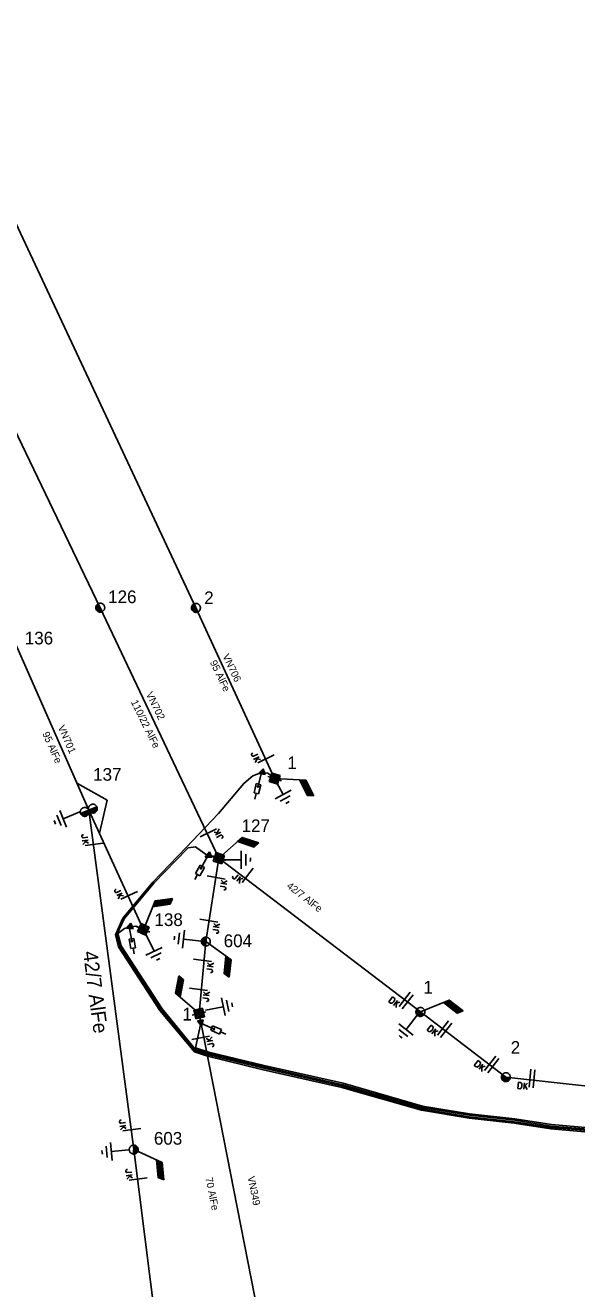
# Model space of a CAD drawing. Extents: x -536397 to -535454, y -1201642 to -1200953.
# Drawn here: x -536253.8 to -536177.8, y -1201334.5 to -1201160.3 of the extents above; entities that cross this region are included whole.
import ezdxf

# ---------------------------------------------------------------- set-up
doc = ezdxf.new("R2010")
doc.units = 0
for name, color, linetype in [('DOPLŇ_POPISY', 7, 'Continuous'), ('ELE_EON', 7, 'Continuous'), ('ELE_EON_POPIS', 7, 'Continuous'), ('Implicitní', 7, 'Continuous'), ('KN_HRAN_PODZEM', 7, 'Continuous'), ('KN_HRAN_POHYBLIVÁ', 7, 'Continuous'), ('KN_HRAN_STÁTNÍ', 7, 'Continuous'), ('KONEC_VEDENÍ', 7, 'Continuous'), ('PB_NN', 7, 'Continuous'), ('PLG_EXPORT_GPE', 7, 'Continuous'), ('PODZEM_NN_POPIS', 7, 'Continuous'), ('PROJEKT', 7, 'Continuous'), ('RÁMEČEK', 7, 'Continuous'), ('SDEL_EON', 7, 'Continuous'), ('SDEL_EON_POPIS', 7, 'Continuous'), ('SR', 7, 'Continuous'), ('TECH_OCHR_PÁSMO_HRAN', 7, 'Continuous')]:
    doc.layers.add(name, color=color, linetype=linetype)

# ---------------------------------------------------------------- blocks, each defined once
blk = doc.blocks.new('VN850')
at = {"layer": 'RÁMEČEK'}
for points in [[(-0.56, 1.43), (-0.56, -1.07)], [(-0.01, 1.43), (-0.01, -1.07)], [(-2.09, -0.54), (-1.78, -0.54)], [(-2.09, -1.41), (-2.09, -0.54)], [(-1.78, -1.41), (-2.09, -1.41)], [(-1.78, -0.54), (-1.66, -0.6)], [(-1.67, -1.35), (-1.78, -1.41)], [(-1.59, -1.2), (-1.67, -1.35)], [(-1.66, -0.6), (-1.59, -0.75)], [(-1.59, -0.75), (-1.55, -0.96)], [(-1.55, -0.96), (-1.59, -1.2)], [(-1.26, -0.54), (-1.26, -1.41)], [(-0.85, -0.54), (-1.26, -1.09)], [(-1.13, -0.92), (-0.77, -1.41)]]:
    blk.add_lwpolyline(points, dxfattribs=at)
blk = doc.blocks.new('VN840')
at = {"layer": 'RÁMEČEK'}
for points in [[(-0.01, 1.41), (-0.01, -1.09)], [(-1.51, -1.24), (-1.51, -1.15)], [(-1.48, -1.35), (-1.51, -1.24)], [(-1.33, -1.42), (-1.48, -1.35)], [(-1.27, -1.42), (-1.33, -1.42)], [(-1.13, -1.35), (-1.27, -1.42)], [(-1.09, -1.24), (-1.13, -1.35)], [(-1.09, -0.59), (-1.09, -1.24)], [(-0.68, -0.59), (-0.68, -1.42)], [(-0.68, -1.11), (-0.27, -0.59)], [(-0.54, -0.94), (-0.2, -1.42)]]:
    blk.add_lwpolyline(points, dxfattribs=at)
blk = doc.blocks.new('VN860')
at = {"layer": 'RÁMEČEK'}
for points in [[(-3.74, 0), (0.01, 2.82)], [(0.01, 2.82), (3.76, 0)]]:
    blk.add_lwpolyline(points, dxfattribs=at)
blk = doc.blocks.new('VN890')
at = {"layer": 'SDEL_EON_POPIS'}
for points in [[(-0.41, 0.41), (0.41, 0)], [(-0.41, -0.41), (-0.41, 0.41)], [(0.41, 0), (-0.41, -0.41)], [(-0.34, 0.31), (0.27, 0), (-0.34, -0.3), (-0.34, 0.31)], [(-0.26, 0.2), (0.1, 0), (-0.26, -0.18), (-0.26, 0.2)], [(-0.19, 0.09), (-0.04, 0), (-0.19, -0.08), (-0.19, 0.09)], [(-0.16, -0.01), (-0.16, 0.03), (-0.13, 0.01), (-0.16, -0.01)]]:
    blk.add_lwpolyline(points, dxfattribs=at)
blk = doc.blocks.new('VN820')
at = {"layer": 'DOPLŇ_POPISY'}
for points in [[(0, 0), (0, -2.1)], [(-0.32, -1.63), (0.34, -1.63)], [(-0.32, -2.95), (-0.32, -1.63)], [(0.34, -1.63), (0.34, -2.95)], [(0.34, -2.95), (-0.32, -2.95)], [(0, -2.1), (-0.12, -1.86)], [(0, -2.1), (0.12, -1.86)], [(0, -2.95), (0, -3.75)]]:
    blk.add_lwpolyline(points, dxfattribs=at)
blk = doc.blocks.new('VN810')
at = {"layer": 'PLG_EXPORT_GPE'}
for points in [[(0, -1.25), (0, -3.75)], [(1.25, -3.75), (-1.25, -3.75)], [(0.77, -4.37), (-0.8, -4.37)], [(0, -5), (-0.25, -5)], [(0.27, -5), (0, -5)]]:
    blk.add_lwpolyline(points, dxfattribs=at)
blk = doc.blocks.new('VN001')
at = {"layer": 'Implicitní'}
for p, q in [((2.02, 3.53), (4.43, 3.53)), ((2.05, 3.58), (4.46, 3.58)), ((2.07, 3.63), (4.49, 3.63)), ((2.1, 3.68), (4.52, 3.68)), ((2.13, 3.73), (2.54, 3.73)), ((1.73, 3.03), (4.14, 3.03)), ((1.76, 3.08), (4.17, 3.08)), ((1.79, 3.13), (4.2, 3.13)), ((1.82, 3.18), (4.23, 3.18)), ((1.85, 3.23), (4.26, 3.23)), ((1.87, 3.28), (4.29, 3.28)), ((1.9, 3.33), (4.32, 3.33)), ((1.93, 3.38), (4.35, 3.38)), ((1.96, 3.43), (4.37, 3.43)), ((1.99, 3.48), (4.4, 3.48))]:
    blk.add_line(p, q, dxfattribs=at)
blk.add_lwpolyline([(2.13, 3.73), (0, 0)], dxfattribs=at)
blk.add_lwpolyline([(4.55, 3.73), (2.13, 3.73), (1.7, 2.98), (4.12, 2.99)], close=True, dxfattribs=at)
blk = doc.blocks.new('VN440')
at = {"layer": 'ELE_EON_POPIS'}
for points in [[(1.22, 0), (1.21, 0.13), (1.19, 0.25), (1.16, 0.38), (1.11, 0.5), (1.05, 0.61), (0.98, 0.72), (0.9, 0.82), (0.81, 0.91), (0.71, 0.99), (0.6, 1.06), (0.49, 1.12), (0.37, 1.16), (0.25, 1.2), (0.12, 1.22), (-0.01, 1.22), (-0.14, 1.22), (-0.26, 1.2), (-0.39, 1.16), (-0.51, 1.12), (-0.62, 1.06), (-0.73, 0.99), (-0.83, 0.91), (-0.92, 0.82), (-1, 0.72), (-1.07, 0.61), (-1.13, 0.5), (-1.18, 0.38), (-1.21, 0.25), (-1.23, 0.13), (-1.24, 0), (-1.23, -0.13), (-1.21, -0.26), (-1.18, -0.38), (-1.13, -0.5), (-1.07, -0.62), (-1, -0.73), (-0.92, -0.83), (-0.83, -0.92), (-0.73, -1), (-0.62, -1.07), (-0.51, -1.13), (-0.39, -1.17), (-0.26, -1.2), (-0.14, -1.23), (-0.01, -1.23), (0.12, -1.23), (0.25, -1.2), (0.37, -1.17), (0.49, -1.13), (0.6, -1.07), (0.71, -1), (0.81, -0.92), (0.9, -0.83), (0.98, -0.73), (1.05, -0.62), (1.11, -0.5), (1.16, -0.38), (1.19, -0.26), (1.21, -0.13), (1.22, 0)], [(-1.24, 0), (1.22, 0)], [(-1.18, -0.34), (1.1, -0.34)], [(-1.01, -0.63), (0.97, -0.63)], [(-0.74, -0.92), (0.68, -0.92)]]:
    blk.add_lwpolyline(points, dxfattribs=at)
blk = doc.blocks.new('VN470')
at = {"layer": 'ELE_EON_POPIS'}
for points in [[(-1.23, 1.22), (1.23, 1.22)], [(-1.23, -1.23), (-1.23, 1.22)], [(-0.92, 0.9), (0.92, 0.9)], [(-0.92, -0.95), (-0.92, 0.9)], [(-0.61, 0.61), (0.61, 0.61)], [(-0.61, -0.62), (-0.61, 0.61)], [(-0.31, -0.27), (-0.31, 0.34)], [(-0.31, 0.34), (0.31, 0.34)], [(0, 1.22), (0, 1.97)], [(0.31, 0.34), (0.31, -0.27)], [(0.61, 0.61), (0.61, -0.62)], [(0.92, 0.9), (0.92, -0.95)], [(1.23, 1.22), (1.23, -1.23)], [(1.23, -1.23), (-1.23, -1.23)], [(0.92, -0.95), (-0.92, -0.95)], [(0.61, -0.62), (-0.61, -0.62)], [(0.31, -0.27), (-0.31, -0.27)], [(0, -1.23), (0, -1.98)]]:
    blk.add_lwpolyline(points, dxfattribs=at)
blk = doc.blocks.new('VN450')
at = {"layer": 'ELE_EON_POPIS'}
for points in [[(0, 0), (-0.01, 0.13), (-0.03, 0.25), (-0.06, 0.38), (-0.11, 0.5), (-0.16, 0.61), (-0.23, 0.72), (-0.31, 0.82), (-0.4, 0.91), (-0.5, 0.99), (-0.61, 1.06), (-0.72, 1.11), (-0.84, 1.16), (-0.97, 1.19), (-1.09, 1.21), (-1.22, 1.22), (-1.35, 1.21), (-1.47, 1.19), (-1.59, 1.16), (-1.71, 1.11), (-1.83, 1.06), (-1.93, 0.99), (-2.03, 0.91), (-2.12, 0.82), (-2.2, 0.72), (-2.27, 0.61), (-2.33, 0.5), (-2.38, 0.38), (-2.41, 0.25), (-2.43, 0.13), (-2.44, 0), (-2.43, -0.13), (-2.41, -0.25), (-2.38, -0.38), (-2.33, -0.5), (-2.27, -0.61), (-2.2, -0.72), (-2.12, -0.82), (-2.03, -0.91), (-1.93, -0.99), (-1.83, -1.06), (-1.71, -1.11), (-1.59, -1.16), (-1.47, -1.19), (-1.35, -1.21), (-1.22, -1.22), (-1.09, -1.21), (-0.97, -1.19), (-0.84, -1.16), (-0.72, -1.11), (-0.61, -1.06), (-0.5, -0.99), (-0.4, -0.91), (-0.31, -0.82), (-0.23, -0.72), (-0.16, -0.61), (-0.11, -0.5), (-0.06, -0.38), (-0.03, -0.25), (-0.01, -0.13), (0, 0)], [(-2.44, 0), (2.44, 0)], [(2.44, 0), (2.43, 0.13), (2.41, 0.25), (2.38, 0.38), (2.33, 0.5), (2.27, 0.61), (2.2, 0.72), (2.12, 0.82), (2.03, 0.91), (1.94, 0.99), (1.83, 1.06), (1.71, 1.11), (1.6, 1.16), (1.47, 1.19), (1.35, 1.21), (1.22, 1.22), (1.09, 1.21), (0.97, 1.19), (0.84, 1.16), (0.72, 1.11), (0.61, 1.06), (0.5, 0.99), (0.4, 0.91), (0.31, 0.82), (0.23, 0.72), (0.16, 0.61), (0.11, 0.5), (0.06, 0.38), (0.03, 0.25), (0.01, 0.13), (0, 0), (0.01, -0.13), (0.03, -0.25), (0.06, -0.38), (0.11, -0.5), (0.16, -0.61), (0.23, -0.72), (0.31, -0.82), (0.4, -0.91), (0.5, -0.99), (0.61, -1.06), (0.72, -1.11), (0.84, -1.16), (0.97, -1.19), (1.09, -1.21), (1.22, -1.22), (1.35, -1.21), (1.47, -1.19), (1.6, -1.16), (1.71, -1.11), (1.83, -1.06), (1.94, -0.99), (2.03, -0.91), (2.12, -0.82), (2.2, -0.72), (2.27, -0.61), (2.33, -0.5), (2.38, -0.38), (2.41, -0.25), (2.43, -0.13), (2.44, 0)], [(-2.4, -0.31), (-0.04, -0.31)], [(-2.26, -0.61), (-0.17, -0.61)], [(-2.01, -0.92), (-0.42, -0.92)], [(0.04, -0.31), (2.4, -0.31)], [(0.17, -0.61), (2.27, -0.61)], [(0.42, -0.92), (2.02, -0.92)]]:
    blk.add_lwpolyline(points, dxfattribs=at)

msp = doc.modelspace()

# ---------------------------------------------------------------- linework, layer by layer
at = {"layer": 'ELE_EON'}
for points in [[(-536219.44, -1201264.18), (-536230.28, -1201240.65), (-536267.93, -1201160.31)], [(-536279.58, -1201165.38), (-536243.47, -1201240.62), (-536227.12, -1201275.16)], [(-536289.66, -1201170.08), (-536254.73, -1201246.52), (-536245.05, -1201268.55)], [(-536245.05, -1201268.55), (-536237.69, -1201284.62)], [(-536229.86, -1201296.57), (-536218.36, -1201355.13), (-536212.54, -1201404.88), (-536207.27, -1201451.49)]]:
    msp.add_lwpolyline(points, dxfattribs=at)
at = {"layer": 'PODZEM_NN_POPIS'}
for points in [[(-536245.05, -1201268.55), (-536238.86, -1201315.34)], [(-536227.12, -1201275.16), (-536228.92, -1201286.65)], [(-536228.92, -1201286.65), (-536229.86, -1201296.57)], [(-536238.86, -1201315.34), (-536232.78, -1201363.5), (-536227.13, -1201407.48), (-536207.27, -1201451.49)]]:
    msp.add_lwpolyline(points, dxfattribs=at)
at = {"layer": 'PROJEKT'}
for points in [[(-536174.08, -1201313.11), (-536181.38, -1201312.49), (-536186.41, -1201311.69), (-536192.65, -1201311.01), (-536199.22, -1201309.92), (-536210.16, -1201306.78), (-536221.01, -1201304.32), (-536228.67, -1201302.47), (-536230.49, -1201301.88), (-536235.26, -1201296.17), (-536240.98, -1201287.39), (-536241.39, -1201285.72), (-536240.35, -1201283.41), (-536236.24, -1201278.45), (-536231.61, -1201273.69), (-536227.17, -1201268.98), (-536223.69, -1201264.85), (-536222.46, -1201263.79), (-536221.26, -1201263.36), (-536220.36, -1201263.43), (-536219.44, -1201264.18)], [(-536174.06, -1201312.91), (-536181.35, -1201312.29), (-536186.38, -1201311.49), (-536192.62, -1201310.81), (-536199.17, -1201309.73), (-536210.1, -1201306.59), (-536220.96, -1201304.13), (-536228.62, -1201302.28), (-536230.43, -1201301.69), (-536235.1, -1201296.05), (-536240.79, -1201287.31), (-536241.2, -1201285.67), (-536240.17, -1201283.51), (-536236.1, -1201278.59), (-536231.47, -1201273.83), (-536231.37, -1201273.73), (-536230.35, -1201273.57), (-536228.63, -1201274.83), (-536227.12, -1201275.16)], [(-536174.04, -1201312.71), (-536181.33, -1201312.09), (-536186.36, -1201311.29), (-536192.6, -1201310.61), (-536199.13, -1201309.53), (-536210.06, -1201306.39), (-536220.92, -1201303.93), (-536228.56, -1201302.08), (-536230.37, -1201301.5), (-536234.94, -1201295.93), (-536240.6, -1201287.23), (-536241.03, -1201285.53), (-536240.15, -1201284.85), (-536239.48, -1201284.67), (-536238.55, -1201284.55), (-536237.53, -1201285.03)], [(-536174.02, -1201312.51), (-536181.3, -1201311.89), (-536186.33, -1201311.09), (-536192.57, -1201310.41), (-536199.08, -1201309.34), (-536210.01, -1201306.2), (-536220.87, -1201303.74), (-536228.51, -1201301.89), (-536230.34, -1201301.29), (-536229.6, -1201297.92), (-536229.77, -1201296.93)]]:
    msp.add_lwpolyline(points, dxfattribs=at)
at = {"layer": 'SDEL_EON_POPIS'}
for points in [[(-536227.12, -1201275.16), (-536199.36, -1201296.36)], [(-536199.36, -1201296.36), (-536187.58, -1201305.35), (-536149.67, -1201309.55)]]:
    msp.add_lwpolyline(points, dxfattribs=at)

# ---------------------------------------------------------------- block references
at = {"layer": 'DOPLŇ_POPISY'}
for name, p, xscale, yscale, rotation in [('VN440', (-536243.47, -1201240.62), 0.5, 0.49999999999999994, -64.4647500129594), ('VN440', (-536230.28, -1201240.65), 0.5, 0.5, -64.87521117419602), ('VN470', (-536219.44, -1201264.18), 0.4999999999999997, 0.49999999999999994, -107.11528296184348), ('VN450', (-536245.05, -1201268.55), 0.49999999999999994, 0.5000000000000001, 22.397824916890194), ('VN470', (-536227.12, -1201275.16), 0.5, 0.5, 71.20198082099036), ('VN470', (-536237.53, -1201284.96), 0.5000000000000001, 0.5000000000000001, -114.08686544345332), ('VN440', (-536228.92, -1201286.66), 0.5000000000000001, 0.5, -96.35033613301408), ('VN470', (-536229.86, -1201296.57), 0.4999999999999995, 0.4999999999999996, -76.94533903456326), ('VN440', (-536199.35, -1201296.36), 0.49999999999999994, 0.5000000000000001, -37.8457360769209), ('VN440', (-536187.57, -1201305.35), 0.5, 0.5, -37.83150002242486), ('VN440', (-536238.86, -1201315.33), 0.5, 0.5000000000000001, 86.69934168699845)]:
    msp.add_blockref(name, p, dxfattribs=dict(at, xscale=xscale, yscale=yscale, rotation=rotation))
at = {"layer": 'KN_HRAN_PODZEM'}
for p, rotation in [((-536221.26, -1201263.36), -160.28570550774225), ((-536228.63, -1201274.83), -154.34267780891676), ((-536239.48, -1201284.67), -158.4331499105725), ((-536229.61, -1201297.92), -78.9704277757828)]:
    msp.add_blockref('VN890', p, dxfattribs=dict(at, rotation=rotation))
at = {"layer": 'KN_HRAN_POHYBLIVÁ'}
for name, p, rotation in [('VN840', (-536220.76, -1201261.54), -64.61845551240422), ('VN860', (-536245.11, -1201268.29), -66.11288332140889), ('VN840', (-536244.45, -1201273.27), -82.48772505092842), ('VN840', (-536228.44, -1201271.57), 116.1480499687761), ('VN840', (-536223.24, -1201277.64), -37.84615556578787), ('VN840', (-536239.63, -1201280.35), -65.56397498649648), ('VN840', (-536227.33, -1201277.84), 80.1997222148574), ('VN840', (-536228.36, -1201283.8), 80.1997222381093), ('VN840', (-536229.22, -1201289.26), 82.13469442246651), ('VN840', (-536229.77, -1201293.24), 82.13469442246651), ('VN850', (-536201.2, -1201295.11), -37.84615554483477), ('VN850', (-536195.91, -1201299.05), -37.83080836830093), ('VN840', (-536229.49, -1201299.89), 101.4130471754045), ('VN850', (-536189.41, -1201303.92), -37.83080836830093), ('VN850', (-536183.71, -1201305.74), -6.180297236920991), ('VN840', (-536239.26, -1201312.62), -82.48772501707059), ('VN840', (-536238.39, -1201319.44), -82.79501113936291)]:
    msp.add_blockref(name, p, dxfattribs=dict(at, rotation=rotation))
at = {"layer": 'KN_HRAN_STÁTNÍ'}
for p, rotation in [((-536221.26, -1201263.36), -13.990508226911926), ((-536228.63, -1201274.83), -28.8901470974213), ((-536239.48, -1201284.67), 10.619655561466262), ((-536229.61, -1201297.92), 66.19975004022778)]:
    msp.add_blockref('VN820', p, dxfattribs=dict(at, rotation=rotation))
at = {"layer": 'RÁMEČEK'}
for p, rotation in [((-536220.03, -1201263.08), 28.219202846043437), ((-536245.11, -1201268.29), -67.60749723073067), ((-536227.79, -1201275.36), 89.79945003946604), ((-536237.69, -1201284.62), 25.76595266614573), ((-536228.29, -1201286.72), -96.34631667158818), ((-536230.2, -1201296.37), 101.36385831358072), ((-536199.02, -1201295.82), -37.84640564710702), ((-536238.23, -1201315.25), -84.65707223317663)]:
    msp.add_blockref('VN810', p, dxfattribs=dict(at, rotation=rotation))
at = {"layer": 'TECH_OCHR_PÁSMO_HRAN'}
for p, rotation in [((-536219.44, -1201264.18), -63.04782218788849), ((-536227.12, -1201275.16), -18.412788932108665), ((-536237.53, -1201285.03), 7.734305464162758), ((-536228.92, -1201286.65), -96.34487777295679), ((-536229.86, -1201296.57), 78.9054638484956), ((-536199.36, -1201296.36), -37.845780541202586), ((-536238.86, -1201315.34), -84.65707223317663)]:
    msp.add_blockref('VN001', p, dxfattribs=dict(at, rotation=rotation))

# ---------------------------------------------------------------- texts
at = {"layer": 'ELE_EON_POPIS'}
for s, rotation, p in [('95 AlFe', 295.382, (-536228.39, -1201248.14)), ('110/22 AlFe', 296.148, (-536239.27, -1201253.62)), ('95 AlFe', 293.833, (-536251.48, -1201257.98)), ('70 AlFe', 281.413, (-536228.99, -1201319.26))]:
    msp.add_text(s, height=1, rotation=rotation, dxfattribs=at).set_placement(p)
at = {"layer": 'KONEC_VEDENÍ'}
for s, p in [('138', (-536236, -1201284.51)), ('1', (-536232.15, -1201297.54))]:
    msp.add_text(s, height=1.75, dxfattribs=at).set_placement(p)
at = {"layer": 'PB_NN'}
msp.add_text('42/7 AlFe', height=2, rotation=277.512, dxfattribs=at).set_placement((-536245.86, -1201288.08))
at = {"layer": 'PLG_EXPORT_GPE'}
for s, p in [('126', (-536242.38, -1201239.99)), ('2', (-536229.15, -1201240.13)), ('136', (-536253.87, -1201245.68)), ('1', (-536217.69, -1201262.88)), ('137', (-536244.45, -1201264.48)), ('127', (-536224, -1201271.56)), ('604', (-536226.46, -1201287.42)), ('1', (-536198.93, -1201293.82)), ('2', (-536186.91, -1201302.13)), ('603', (-536236.08, -1201314.66))]:
    msp.add_text(s, height=1.75, dxfattribs=at).set_placement(p)
at = {"layer": 'SDEL_EON'}
for s, rotation, p in [('VN706', 295.382, (-536226.65, -1201247.28)), ('VN702', 296.148, (-536237.2, -1201252.53)), ('VN701', 293.833, (-536249.34, -1201257.09)), ('VN349', 281.413, (-536223.18, -1201319.11))]:
    msp.add_text(s, height=1, rotation=rotation, dxfattribs=at).set_placement(p)
at = {"layer": 'SR'}
msp.add_text('42/7 AlFe', height=1, rotation=322.154, dxfattribs=at).set_placement((-536217.87, -1201279.15))

doc.saveas('drawing.dxf')
